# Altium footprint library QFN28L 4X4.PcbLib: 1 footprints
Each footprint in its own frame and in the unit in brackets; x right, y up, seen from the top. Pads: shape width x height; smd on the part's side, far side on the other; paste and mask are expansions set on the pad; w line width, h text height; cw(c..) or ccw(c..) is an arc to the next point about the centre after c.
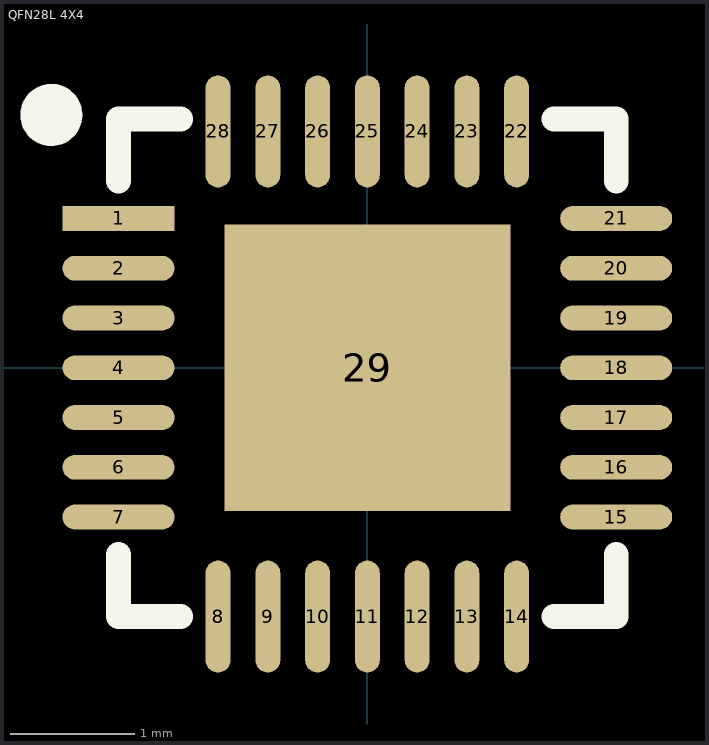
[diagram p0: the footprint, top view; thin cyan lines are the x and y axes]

## QFN28L 4X4 [mm] "QFN, 28-Leads, Body 4.00x4.00mm, Pitch 0.40mm, Thermal Pad 2.30x2.30mm, IPC Medium Density"
height 0.8
pads (29):
  rect 0.9x0.2 smd: 1(-2,1.2)
  oval 0.9x0.2 smd: 2(-2,0.8) 3(-2,0.4) 4(-2,0) 5(-2,-0.4) 6(-2,-0.8) 7(-2,-1.2) 15(2,-1.2) 16(2,-0.8) 17(2,-0.4) 18(2,0) 19(2,0.4) 20(2,0.8) 21(2,1.2)
  oval 0.2x0.9 smd: 8(-1.2,-2) 9(-0.8,-2) 10(-0.4,-2) 11(0,-2) 12(0.4,-2) 13(0.8,-2) 14(1.2,-2) 22(1.2,1.9) 23(0.8,1.9) 24(0.4,1.9) 25(0,1.9) 26(-0.4,1.9) 27(-0.8,1.9) 28(-1.2,1.9)
  rect 2.3x2.3 smd: 29(0,0)
Top Overlay:
  circle w0.25: c-2.54,2.032 r0.125
  lines w0.2: -2,-1.5 -2,-2 -1.5,-2 ; -2,1.5 -2,2 -1.5,2 ; 1.5,-2 2,-2 2,-1.5 ; 1.5,2 2,2 2,1.5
